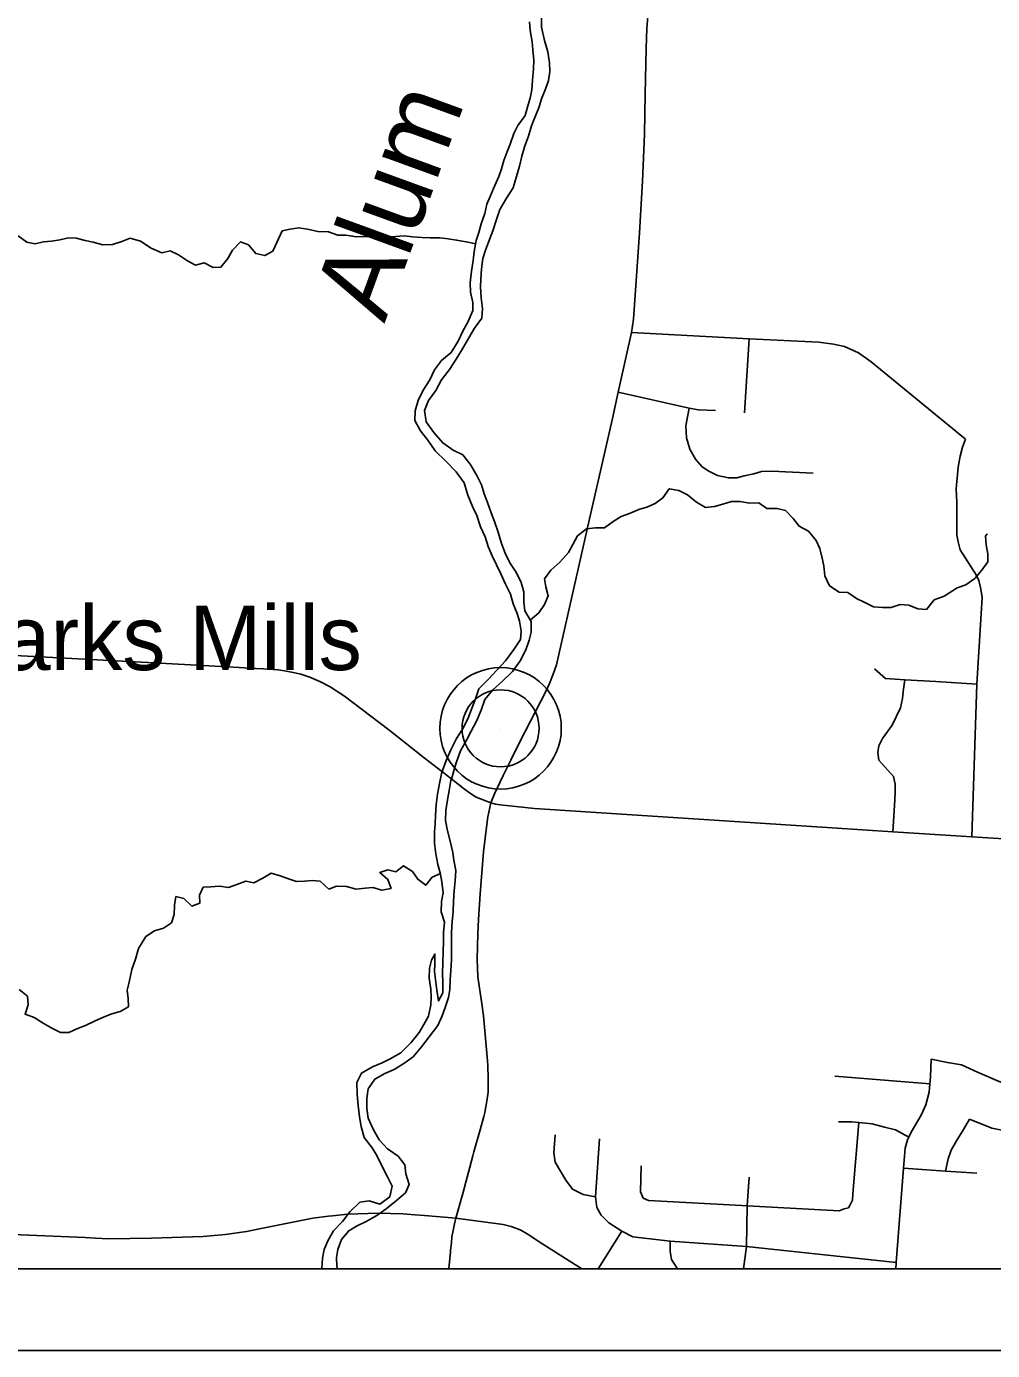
# Model space of a CAD drawing. Extents: x 0 to 34, y 0 to 22.
# Drawn here: x 4.152 to 5.335, y 14 to 15.622 of the extents above; entities that cross this region are included whole.
import ezdxf

# ---------------------------------------------------------------- set-up
doc = ezdxf.new("R2010")
doc.units = 0
for name, color, linetype in [('GM_X_City_Street', 7, 'Continuous'), ('GM_X_Corporation', 7, 'Continuous'), ('GM_X_County_Road', 7, 'Continuous'), ('GM_X_Major_River', 7, 'Continuous'), ('GM_X_Major_River_Text', 7, 'Continuous'), ('GM_X_Minor_River', 7, 'Continuous'), ('GM_X_Unincorporated', 7, 'Continuous'), ('GM_X_Unincorporated_Location', 7, 'Continuous'), ('GM_X_Unincorporated_Text', 7, 'Continuous'), ('SH_Data', 7, 'Continuous')]:
    doc.layers.add(name, color=color, linetype=linetype)

msp = doc.modelspace()

# ---------------------------------------------------------------- linework, layer by layer
at = {"layer": 'GM_X_City_Street'}
for p, q in [((5.0314, 15.1488), (5.0368, 15.2396)), ((5.1417, 14.3361), (5.2583, 14.3268)), ((4.8519, 14.1), (4.8812, 14.1462))]:
    msp.add_line(p, q, dxfattribs=at)
for points in [[(4.8929, 15.2474), (5.0368, 15.2396), (5.1222, 15.2353), (5.1404, 15.2328), (5.1539, 15.23), (5.1707, 15.2222), (5.1863, 15.2115), (5.302, 15.1164)], [(4.8766, 15.1741), (4.9635, 15.1545), (4.9748, 15.1524), (4.9958, 15.1517)], [(4.9635, 15.1545), (4.9595, 15.1328), (4.9602, 15.1182), (4.9641, 15.1043), (4.9713, 15.0922), (4.9791, 15.0833), (4.9866, 15.0776), (4.9983, 15.0719), (5.0115, 15.0691), (5.0218, 15.0694), (5.0307, 15.0715), (5.0428, 15.074), (5.0521, 15.0769), (5.0649, 15.0772), (5.1155, 15.0751)], [(5.3096, 14.6293), (5.3158, 14.8165), (5.3223, 14.9224), (5.3209, 14.9327), (5.3182, 14.9433), (5.3148, 14.9505), (5.2956, 14.981), (5.2929, 14.9908), (5.2915, 14.9992), (5.2915, 15.0151), (5.2912, 15.039), (5.2904, 15.0557), (5.2928, 15.0823), (5.2955, 15.0959), (5.2981, 15.1066), (5.302, 15.1164)], [(5.1903, 14.8351), (5.2039, 14.8233), (5.2275, 14.8219), (5.2658, 14.8195), (5.3158, 14.8165)], [(5.2131, 14.6355), (5.2151, 14.6676), (5.2157, 14.6835), (5.2156, 14.6939), (5.2138, 14.7033), (5.1957, 14.7235), (5.1946, 14.7326), (5.1958, 14.741), (5.2003, 14.7497), (5.2121, 14.7663), (5.2224, 14.7876), (5.2247, 14.799), (5.2255, 14.8073), (5.2275, 14.8219)], [(5.2165, 14.1), (5.2171, 14.1077), (5.226, 14.2233), (5.2279, 14.248), (5.2311, 14.2582), (5.2325, 14.2613), (5.2354, 14.2676), (5.2478, 14.2883), (5.2533, 14.3011), (5.2573, 14.3166), (5.2583, 14.3268), (5.2591, 14.3352), (5.2598, 14.3568)], [(5.2598, 14.3568), (5.2798, 14.3527), (5.2972, 14.3502), (5.3168, 14.3412), (5.3431, 14.3298), (5.3589, 14.3235), (5.3699, 14.3219), (5.399, 14.3192), (5.4758, 14.3129), (5.4997, 14.3109)], [(5.3068, 14.2833), (5.3343, 14.2723), (5.3483, 14.2694), (5.4357, 14.2602), (5.4429, 14.262), (5.4498, 14.2661), (5.4753, 14.2995), (5.4761, 14.3044), (5.4758, 14.3129)], [(5.1462, 14.2802), (5.1629, 14.28), (5.1711, 14.2792), (5.1878, 14.2777), (5.2029, 14.2737), (5.2161, 14.2705), (5.2325, 14.2613)], [(5.1587, 14.1749), (5.1607, 14.1783), (5.1634, 14.1843), (5.1639, 14.1919), (5.1711, 14.2792)], [(5.2775, 14.2198), (5.2808, 14.2347), (5.2843, 14.2453), (5.2909, 14.2569), (5.2995, 14.2709), (5.3068, 14.2833)], [(4.8488, 14.1883), (4.8336, 14.191), (4.8204, 14.1978), (4.8123, 14.2086), (4.7992, 14.2308), (4.7978, 14.2423), (4.7995, 14.2642)], [(4.8812, 14.1462), (4.8651, 14.1565), (4.8555, 14.1657), (4.8505, 14.1752), (4.8488, 14.1883), (4.8535, 14.2592)], [(4.907, 14.1868), (4.9037, 14.1944), (4.9045, 14.2263)], [(5.0302, 14.1), (5.0336, 14.1273), (5.0345, 14.1773), (5.0369, 14.2123)], [(5.226, 14.2233), (5.2775, 14.2198), (5.3158, 14.2171)], [(4.907, 14.1868), (4.9138, 14.1837), (5.028, 14.1776), (5.0345, 14.1773), (5.1473, 14.1713), (5.1534, 14.1735), (5.1587, 14.1749)], [(4.8812, 14.1462), (4.8946, 14.1394), (4.9402, 14.134), (5.0336, 14.1273), (5.2171, 14.1077)], [(4.9493, 14.1), (4.9419, 14.1114), (4.9402, 14.1212), (4.9402, 14.134)]]:
    msp.add_lwpolyline(points, dxfattribs=at)
at = {"layer": 'GM_X_Corporation'}
msp.add_lwpolyline([(2.1, 20.9), (2.1, 14.1), (6.2395, 14.1)], dxfattribs=at)
at = {"layer": 'GM_X_County_Road'}
for p, q in [((4.6177, 14.1671), (4.6276, 14.1664)), ((4.7358, 14.1543), (4.6779, 14.1623)), ((4.6693, 14.1), (4.6711, 14.1209))]:
    msp.add_line(p, q, dxfattribs=at)
for points in [[(5.4989, 16.2977), (5.2615, 16.3089), (5.0301, 16.3238), (4.7825, 16.3404), (4.4809, 16.3594), (4.0961, 16.3837), (3.9805, 16.3916), (3.8512, 16.4005), (3.654, 16.4154), (3.6418, 16.2257), (3.634, 16.1053), (3.6204, 15.8961), (3.6146, 15.8068), (3.6105, 15.7435), (3.6083, 15.7281), (3.6065, 15.7173), (3.5547, 14.8664), (3.5412, 14.6736), (3.5067, 14.1788), (3.5033, 14.1), (8.2619, 14.1)], [(4.7163, 14.3551), (4.715, 14.3733), (4.7117, 14.4102), (4.7093, 14.4278), (4.7048, 14.4578), (4.7039, 14.4795), (4.7047, 14.5104), (4.7055, 14.528), (4.7073, 14.5594), (4.7114, 14.6111), (4.7149, 14.6381), (4.7168, 14.6538), (4.7207, 14.6709), (4.725, 14.682), (4.7357, 14.7044), (4.7451, 14.7235), (4.7569, 14.7473), (4.7875, 14.8068), (4.7925, 14.8171), (4.7971, 14.8288), (4.801, 14.84), (4.8416, 15.019), (4.8694, 15.142), (4.8766, 15.1741), (4.8877, 15.2236), (4.8929, 15.2474), (4.8952, 15.2638), (4.9025, 15.3694), (4.9062, 15.4325), (4.9089, 15.4901), (4.9097, 15.5387), (4.9108, 15.5956), (4.9117, 15.6199), (4.9131, 15.6395)], [(3.8359, 14.8671), (3.926, 14.8621), (4.1376, 14.8515), (4.3005, 14.8428), (4.4125, 14.8367), (4.4323, 14.8358)], [(4.4323, 14.8358), (4.4422, 14.8353), (4.4595, 14.8338), (4.4679, 14.8326), (4.4784, 14.8307), (4.4879, 14.8285), (4.4989, 14.8248), (4.5118, 14.8193), (4.5236, 14.8131), (4.5412, 14.8016), (4.5958, 14.7603), (4.6391, 14.7263)], [(4.6391, 14.7263), (4.6619, 14.7084), (4.6806, 14.6937), (4.6883, 14.6878), (4.6956, 14.6825), (4.7026, 14.6781), (4.7207, 14.6709)], [(4.7207, 14.6709), (4.7263, 14.6694), (4.7321, 14.6686), (4.774, 14.664), (5.1388, 14.6403), (5.2131, 14.6355), (5.3096, 14.6293), (5.3752, 14.6253), (5.4513, 14.6217), (5.5487, 14.6179), (5.6766, 14.611), (5.7928, 14.6041), (5.9153, 14.5984), (5.9347, 14.599), (6.0376, 14.5926), (6.2763, 14.5811), (6.2937, 14.5803), (6.3046, 14.5797)], [(4.7121, 14.2867), (4.7134, 14.2915), (4.7157, 14.3055), (4.7172, 14.3165), (4.7175, 14.3249), (4.7175, 14.3333), (4.7167, 14.3491), (4.7163, 14.3551)], [(4.6986, 14.2387), (4.6999, 14.2435), (4.7076, 14.2702), (4.7121, 14.2867)], [(4.6779, 14.1623), (4.6861, 14.1924), (4.6986, 14.2387)], [(4.4372, 14.149), (4.4678, 14.1554), (4.5025, 14.162), (4.5216, 14.1646), (4.5267, 14.1651)], [(4.5267, 14.1651), (4.545, 14.1669), (4.5827, 14.1681), (4.6128, 14.1674), (4.6177, 14.1671)], [(4.6276, 14.1664), (4.6394, 14.1656), (4.6779, 14.1623)], [(4.6722, 14.132), (4.6729, 14.1391), (4.6743, 14.1469), (4.676, 14.1553), (4.6779, 14.1623)], [(3.8044, 14.161), (3.9542, 14.1532), (4.0651, 14.1455), (4.1448, 14.1418), (4.2237, 14.1384), (4.2365, 14.1377)], [(4.3772, 14.1406), (4.3956, 14.142), (4.4214, 14.1457), (4.4372, 14.149)], [(4.8321, 14.1), (4.7798, 14.1333), (4.7659, 14.1426), (4.7565, 14.148), (4.7455, 14.1519), (4.7358, 14.1543)], [(4.2365, 14.1377), (4.2524, 14.1367), (4.305, 14.1376), (4.3681, 14.1399), (4.3772, 14.1406)], [(4.6711, 14.1209), (4.6711, 14.1219), (4.6712, 14.1228), (4.6722, 14.132)]]:
    msp.add_lwpolyline(points, dxfattribs=at)
at = {"layer": 'GM_X_Major_River'}
for points in [[(4.7681, 15.6279), (4.7688, 15.6173), (4.771, 15.6036), (4.7721, 15.5938), (4.7732, 15.5808), (4.7728, 15.5702), (4.7716, 15.5565), (4.7707, 15.5444), (4.7688, 15.5345), (4.7657, 15.5251), (4.7626, 15.5133), (4.7535, 15.5008), (4.7489, 15.491), (4.7442, 15.4781), (4.74, 15.4678), (4.7366, 15.458), (4.7338, 15.4477), (4.7304, 15.4383), (4.7239, 15.4239), (4.7196, 15.414), (4.7158, 15.4046), (4.7131, 15.3932), (4.7089, 15.3803), (4.7058, 15.3697), (4.7027, 15.3598), (4.7003, 15.3465), (4.6988, 15.3355), (4.6968, 15.3226), (4.6952, 15.3082), (4.6955, 15.2968), (4.6985, 15.2839), (4.6985, 15.2744), (4.6927, 15.2608), (4.6862, 15.249), (4.6805, 15.2365), (4.672, 15.2229), (4.6602, 15.2131), (4.6515, 15.2017), (4.6457, 15.1892), (4.6377, 15.1767), (4.6315, 15.1638), (4.6277, 15.1513), (4.6276, 15.1396), (4.6344, 15.127), (4.6434, 15.1152), (4.6525, 15.1022), (4.6657, 15.0893), (4.6781, 15.0767), (4.6879, 15.063), (4.6924, 15.0481), (4.698, 15.0341), (4.7033, 15.023), (4.7078, 15.0093), (4.7138, 14.9968), (4.7171, 14.985)], [(4.7826, 15.6347), (4.7825, 15.6214), (4.7862, 15.6051), (4.7903, 15.591), (4.7925, 15.5777), (4.7928, 15.5671), (4.7913, 15.5561), (4.7878, 15.5466), (4.7828, 15.5337), (4.7797, 15.5239), (4.7744, 15.5106), (4.7705, 15.5004), (4.7667, 15.4878), (4.7624, 15.4761), (4.7586, 15.4632), (4.7555, 15.4511), (4.7478, 15.4245), (4.7397, 15.412), (4.7317, 15.398), (4.7275, 15.3859), (4.7232, 15.3719), (4.7178, 15.3578), (4.714, 15.348), (4.7109, 15.3381), (4.7093, 15.3252), (4.7085, 15.3127), (4.7081, 15.3032), (4.7088, 15.2899), (4.7102, 15.2766), (4.7094, 15.2649), (4.7006, 15.2524), (4.6938, 15.2406), (4.6857, 15.2274), (4.6781, 15.2145), (4.67, 15.202), (4.6601, 15.1892), (4.6532, 15.1763), (4.6441, 15.1638), (4.6395, 15.1517), (4.6413, 15.138), (4.6507, 15.1247), (4.6616, 15.1121), (4.6745, 15.1033), (4.6862, 15.0975), (4.6953, 15.0861), (4.7032, 15.0731), (4.7092, 15.0606), (4.7125, 15.0496), (4.7163, 15.0389), (4.7211, 15.0264), (4.7249, 15.0157), (4.7297, 15.0028), (4.7335, 14.9887), (4.738, 14.9769), (4.744, 14.9651), (4.7519, 14.9529), (4.7579, 14.9411), (4.7609, 14.9297), (4.7608, 14.9168), (4.7623, 14.9062), (4.7698, 14.8933), (4.7701, 14.8803), (4.7674, 14.8705), (4.7635, 14.8584), (4.7563, 14.8451), (4.7471, 14.8319), (4.7349, 14.8201), (4.7231, 14.8096), (4.7132, 14.7975), (4.7086, 14.7846), (4.7032, 14.7709)], [(4.7171, 14.985), (4.722, 14.9736), (4.7329, 14.9515), (4.7385, 14.939), (4.7445, 14.9268), (4.7479, 14.915), (4.7528, 14.9032), (4.7558, 14.8937), (4.7576, 14.8812), (4.7568, 14.8713), (4.7488, 14.8588), (4.7385, 14.8452), (4.7285, 14.8338), (4.7171, 14.8221), (4.706, 14.8108), (4.7018, 14.7983), (4.6976, 14.7877), (4.6922, 14.774), (4.6857, 14.7611), (4.6784, 14.7498), (4.6715, 14.7358), (4.6662, 14.7237), (4.6604, 14.7085), (4.6577, 14.6948), (4.6553, 14.6816), (4.6538, 14.6687), (4.6529, 14.6558), (4.6525, 14.6451), (4.6517, 14.6353), (4.6516, 14.6216), (4.6531, 14.6087), (4.6557, 14.5954), (4.6587, 14.5851), (4.6605, 14.5741), (4.6623, 14.5608), (4.66, 14.5502), (4.6599, 14.5373), (4.6637, 14.5247), (4.6625, 14.5122), (4.6624, 14.5008), (4.662, 14.4887), (4.6619, 14.475), (4.6615, 14.4621), (4.6618, 14.4507), (4.6617, 14.4382), (4.6564, 14.4283), (4.6545, 14.4416), (4.6527, 14.4545), (4.6516, 14.4644), (4.652, 14.4739), (4.6521, 14.4857), (4.648, 14.4784), (4.6453, 14.4683), (4.6451, 14.4561), (4.647, 14.4428), (4.6473, 14.4329), (4.6469, 14.4234), (4.6441, 14.4098), (4.6384, 14.3996), (4.6327, 14.3897), (4.6231, 14.3772), (4.6105, 14.3648), (4.5972, 14.3572), (4.5873, 14.3523), (4.5756, 14.3475), (4.5622, 14.3399), (4.5565, 14.3282), (4.5568, 14.3138), (4.5579, 14.3001), (4.5597, 14.2864), (4.5619, 14.2746), (4.5653, 14.2609), (4.5751, 14.2484), (4.5811, 14.2389), (4.5871, 14.2263), (4.5942, 14.213), (4.5999, 14.2012), (4.5968, 14.1883), (4.5846, 14.1792), (4.5717, 14.1835), (4.56, 14.1816), (4.5478, 14.1699), (4.539, 14.1582), (4.5279, 14.1465), (4.521, 14.1344), (4.5164, 14.1237), (4.5145, 14.1131), (4.5137, 14.1)], [(4.7032, 14.7709), (4.6963, 14.7588), (4.6906, 14.7478), (4.6833, 14.7346), (4.6787, 14.7213), (4.6756, 14.7118), (4.6732, 14.703)], [(4.6732, 14.703), (4.6717, 14.6982), (4.6694, 14.686), (4.6674, 14.6747), (4.6655, 14.6618), (4.665, 14.6492), (4.6676, 14.6367), (4.6706, 14.6242), (4.6739, 14.6101), (4.6754, 14.6006), (4.6776, 14.5881), (4.6768, 14.5755), (4.6756, 14.5634), (4.6748, 14.5505), (4.6744, 14.538), (4.6732, 14.5254), (4.6723, 14.5125), (4.6722, 14.4787), (4.6717, 14.4662), (4.6709, 14.4541), (4.6705, 14.4423), (4.6689, 14.4324), (4.6647, 14.4203), (4.6608, 14.4101), (4.6558, 14.3983), (4.6452, 14.3843), (4.6356, 14.3722), (4.6253, 14.3598), (4.6139, 14.3515), (4.6021, 14.3443), (4.5907, 14.3394), (4.5785, 14.3326), (4.5705, 14.3205), (4.5685, 14.3088), (4.5685, 14.2966), (4.5703, 14.2845), (4.5763, 14.2711), (4.5838, 14.2582), (4.594, 14.2471), (4.6069, 14.238), (4.6152, 14.2277), (4.6166, 14.2163), (4.6207, 14.2034), (4.6161, 14.1931), (4.6051, 14.1837), (4.5925, 14.1735), (4.5811, 14.1656), (4.5678, 14.158), (4.556, 14.1524), (4.5465, 14.1468), (4.5377, 14.1362), (4.5331, 14.1237), (4.5316, 14.1138), (4.5319, 14.1039), (4.5327, 14.1)]]:
    msp.add_lwpolyline(points, dxfattribs=at)
at = {"layer": 'GM_X_Minor_River'}
for points in [[(4.702, 15.3559), (4.6905, 15.3582), (4.6787, 15.3606), (4.6685, 15.3619), (4.6579, 15.3631), (4.6462, 15.3632), (4.636, 15.3637), (4.6246, 15.3645), (4.6144, 15.3658), (4.6037, 15.3647), (4.5931, 15.3645), (4.5818, 15.365), (4.5689, 15.3647), (4.5564, 15.3644), (4.5431, 15.3665), (4.5333, 15.3666), (4.5216, 15.3708), (4.5087, 15.371), (4.4962, 15.3737), (4.4852, 15.3757), (4.4746, 15.3739), (4.4651, 15.3718), (4.4585, 15.3574), (4.4535, 15.3468), (4.4436, 15.3416), (4.4326, 15.344), (4.4236, 15.3547), (4.4138, 15.3582), (4.4042, 15.348), (4.3985, 15.3378), (4.39, 15.3273), (4.3806, 15.327), (4.3696, 15.3328), (4.359, 15.3298), (4.3492, 15.3349), (4.3379, 15.3426), (4.3277, 15.3472), (4.3178, 15.345), (4.3046, 15.3505), (4.2914, 15.359), (4.2789, 15.3629), (4.2687, 15.3588), (4.2573, 15.3551), (4.2455, 15.3545), (4.2334, 15.358), (4.2236, 15.36), (4.2126, 15.3627), (4.2031, 15.3632), (4.1925, 15.361), (4.1823, 15.3592), (4.1728, 15.3582), (4.1625, 15.356), (4.1523, 15.358), (4.1418, 15.3657)], [(4.7688, 14.8949), (4.7792, 14.904), (4.7861, 14.9142), (4.7908, 14.9247), (4.7878, 14.9358), (4.7864, 14.9453), (4.7941, 14.9562), (4.8052, 14.966), (4.8155, 14.9777), (4.8209, 14.9875), (4.8267, 14.9981), (4.8377, 15.0067), (4.8487, 15.0081), (4.8597, 15.008), (4.8704, 15.0159), (4.88, 15.0219), (4.8906, 15.0256), (4.902, 15.0304), (4.9115, 15.0333), (4.9218, 15.0378), (4.9313, 15.0449), (4.939, 15.0559), (4.9507, 15.0539), (4.9613, 15.0484), (4.9726, 15.0396), (4.9835, 15.033), (4.9945, 15.0341), (5.0048, 15.037), (5.0154, 15.0403), (5.026, 15.0402), (5.0374, 15.0382), (5.0488, 15.0385), (5.0585, 15.0316), (5.0711, 15.0318), (5.0813, 15.0291), (5.091, 15.0195), (5.0981, 15.0099), (5.1098, 15.0037), (5.1192, 14.9923), (5.1237, 14.9827), (5.1262, 14.9709), (5.1284, 14.9614), (5.1298, 14.9493), (5.1354, 14.9371), (5.1474, 14.9293), (5.158, 14.9289), (5.1686, 14.9215), (5.1788, 14.9165), (5.1893, 14.9111), (5.2003, 14.9102), (5.2109, 14.9105), (5.222, 14.9142), (5.2326, 14.9133), (5.2435, 14.9087), (5.2541, 14.9078), (5.2637, 14.9199), (5.2759, 14.9243), (5.2919, 14.9344), (5.3025, 14.9381), (5.3132, 14.946), (5.322, 14.9562), (5.3293, 14.9664), (5.3294, 14.9762), (5.3272, 14.9873), (5.3266, 14.9979), (5.3285, 15.0005)], [(4.6588, 14.5844), (4.6486, 14.5801), (4.6409, 14.57), (4.6311, 14.5773), (4.6247, 14.5868), (4.6138, 14.5938), (4.6043, 14.5863), (4.5944, 14.589), (4.5846, 14.5857), (4.5943, 14.5772), (4.5984, 14.5662), (4.587, 14.564), (4.576, 14.5672), (4.5666, 14.5665), (4.5556, 14.5651), (4.5438, 14.5686), (4.5317, 14.5691), (4.5222, 14.5654), (4.5117, 14.575), (4.5018, 14.5758), (4.4924, 14.5752), (4.4825, 14.5745), (4.4727, 14.578), (4.4625, 14.5815), (4.4515, 14.5847), (4.4412, 14.5787), (4.4302, 14.5731), (4.4204, 14.5751), (4.4093, 14.571), (4.3991, 14.5673), (4.3881, 14.5689), (4.3778, 14.5683), (4.3684, 14.5676), (4.3637, 14.5578), (4.364, 14.5479), (4.3545, 14.5446), (4.3447, 14.5538), (4.3349, 14.5562), (4.3333, 14.5455), (4.3328, 14.5342), (4.3293, 14.5239), (4.3198, 14.5176), (4.3088, 14.5143), (4.2981, 14.5071), (4.2892, 14.4924), (4.2853, 14.4795), (4.2807, 14.4667), (4.2775, 14.4515), (4.2751, 14.4417), (4.2762, 14.4314), (4.2768, 14.4211), (4.2666, 14.4152), (4.2563, 14.4126), (4.2468, 14.4089), (4.235, 14.4037), (4.2243, 14.3981), (4.2137, 14.394), (4.2038, 14.3896), (4.1936, 14.3897), (4.183, 14.3951), (4.1724, 14.4012), (4.1611, 14.4082), (4.1502, 14.4121), (4.1537, 14.4235), (4.153, 14.4341), (4.1429, 14.4425)]]:
    msp.add_lwpolyline(points, dxfattribs=at)
at = {"layer": 'GM_X_Unincorporated'}
for radius in [0.0744, 0.0472]:
    msp.add_circle((4.7325, 14.7623), radius, dxfattribs=at)
at = {"layer": 'GM_X_Unincorporated_Location'}
msp.add_line((4.7325, 14.7623), (4.7325, 14.7623), dxfattribs=at)
at = {"layer": 'SH_Data'}
for p, q in [((2.1, 14.1), (8.9, 14.1)), ((2, 14), (9, 14))]:
    msp.add_line(p, q, dxfattribs=at)

# ---------------------------------------------------------------- texts
at = {"layer": 'GM_X_Major_River_Text'}
msp.add_text('Alum', height=0.0947, rotation=69.9993, dxfattribs=at).set_placement((4.5902, 15.2577))
at = {"layer": 'GM_X_Unincorporated_Text'}
msp.add_text('Parks Mills', height=0.078977, rotation=0, dxfattribs=at).set_placement((4.0521, 14.8337))

doc.saveas('drawing.dxf')
